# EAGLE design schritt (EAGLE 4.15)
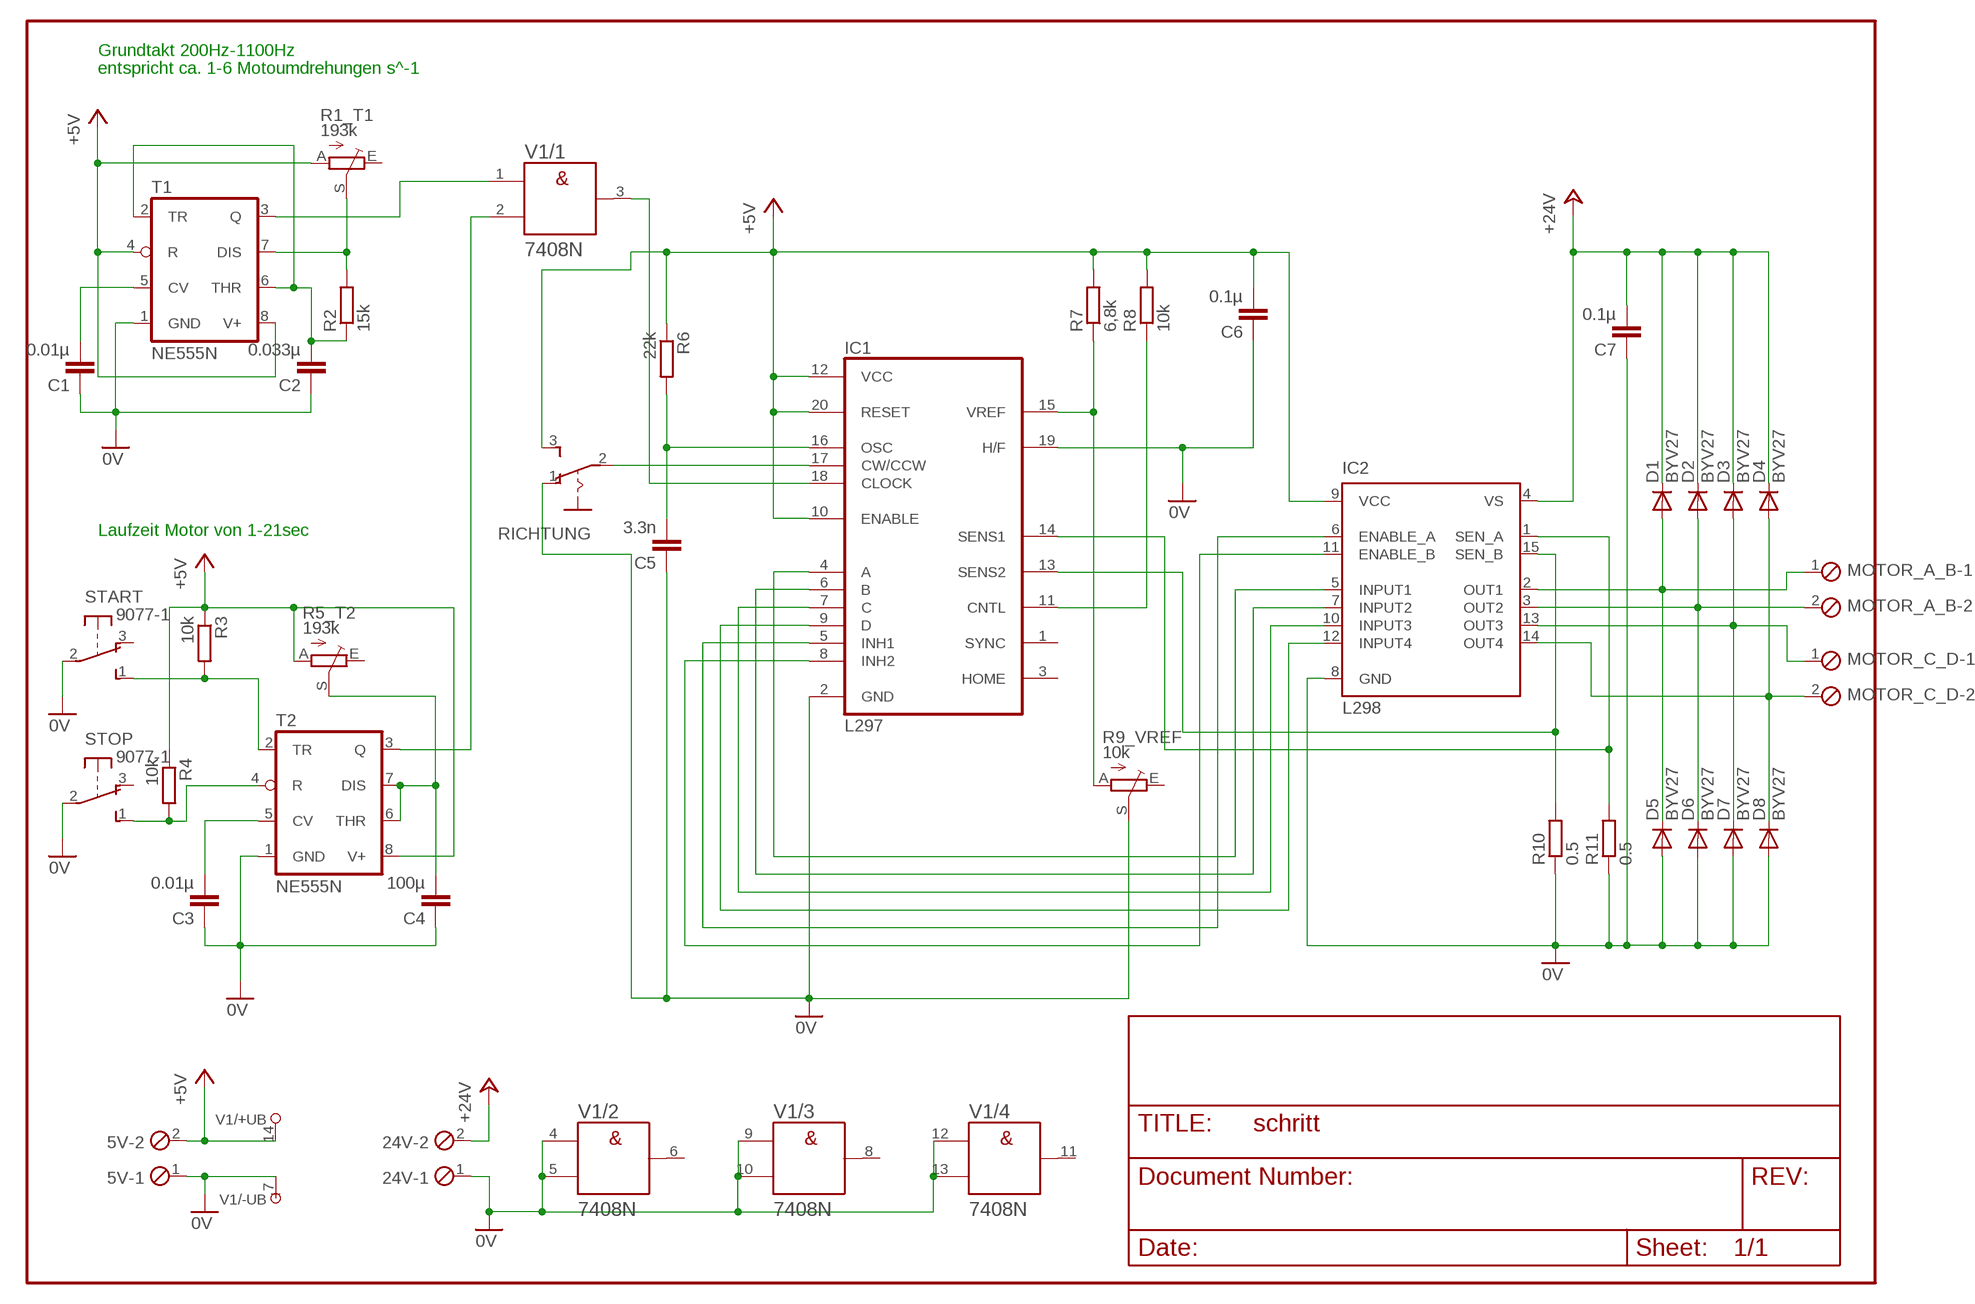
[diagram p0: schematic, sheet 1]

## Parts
5V  MPT2  [2POL254]
24V  MPT2  [2POL254]
C1  0.01µ  C-EU025-030X050  [C025-030X050]
C2  0.033µ  C-EU025-030X050  [C025-030X050]
C3  0.01µ  C-EU025-030X050  [C025-030X050]
C4  100µ  C-EU025-030X050  [C025-030X050]
C5  3.3n  C-EU025-030X050  [C025-030X050]
C6  0.1µ  C-EU025-030X050  [C025-030X050]
C7  0.1µ  C-EU025-030X050  [C025-030X050]
D1  BYV27  [SOD57-10]
D2  BYV27  [SOD57-10]
D3  BYV27  [SOD57-10]
D4  BYV27  [SOD57-10]
D5  BYV27  [SOD57-10]
D6  BYV27  [SOD57-10]
D7  BYV27  [SOD57-10]
D8  BYV27  [SOD57-10]
IC1  L297  [DIL20]
IC2  L298  [MULTIWATT-15]
MOTOR_A_B  MPT2  [2POL254]
MOTOR_C_D  MPT2  [2POL254]
R1_T1  193k  TRIM_EU-CA14H  [CA14H]
R2  15k  R-EU_0204/5  [0204/5]
R3  10k  R-EU_0204/5  [0204/5]
R4  10k  R-EU_0204/5  [0204/5]
R5_T2  193k  TRIM_EU-CA14H  [CA14H]
R6  22k  R-EU_0204/5  [0204/5]
R7  6,8k  R-EU_0204/5  [0204/5]
R8  10k  R-EU_0204/5  [0204/5]
R9_VREF  10k  TRIM_EU-B25U  [B25U]
R10  0.5  R-EU_0207/12  [0207/12]
R11  0.5  R-EU_0207/12  [0207/12]
RICHTUNG  255SB  [255SB]
START  9077-1  [9077-1]
STOP  9077-1  [9077-1]
T1  NE555N  [DIL08]
T2  NE555N  [DIL08]
V1  7408N  [DIL14]

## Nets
0V: 5V.1 24V.1 C1.1 C2.1 C3.1 C4.1 C5.1 C6.1 C7.1 D5.A D6.A D7.A D8.A IC1.2(GND) IC1.19(H/F) IC2.8(GND) R9_VREF.S R10.1 R11.1 RICHTUNG.1(O) START.2(P) STOP.2(P) T1.1(GND) T2.1(GND) V1.4(/2:A) V1.5(/2:B) V1.7(/-UB:-UB) V1.9(/3:A) V1.10(/3:B) V1.12(/4:A) V1.13(/4:B)
+5V: 5V.2 C6.2 IC1.10(ENABLE) IC1.12(VCC) IC1.20(RESET) IC2.9(VCC) R1_T1.A R3.1 R4.1 R5_T2.A R6.1 R7.2 R8.2 RICHTUNG.3(S) T1.4(R) T1.8(V+) T2.8(V+) V1.14(/+UB:+UB)
+24V: 24V.2 C7.2 D1.C D2.C D3.C D4.C IC2.4(VS)
N$1: T2.3(Q) V1.2(/1:B)
N$2: T1.3(Q) V1.1(/1:A)
N$3: C1.2 C3.2 T1.5(CV) T2.5(CV)
N$4: R1_T1.S R2.2 T1.7(DIS)
N$5: C2.2 R2.1 T1.2(TR) T1.6(THR)
N$7: IC1.18(CLOCK) V1.3(/1:Y)
N$8: R3.2 START.1(S) T2.2(TR)
N$9: R4.2 STOP.1(S) T2.4(R)
N$10: IC1.4(A) IC2.5(INPUT1)
N$11: IC1.6(B) IC2.7(INPUT2)
N$12: IC1.7(C) IC2.10(INPUT3)
N$13: IC1.9(D) IC2.12(INPUT4)
N$14: IC1.5(INH1) IC2.6(ENABLE_A)
N$15: C4.2 R5_T2.S T2.6(THR) T2.7(DIS)
N$16: IC1.8(INH2) IC2.11(ENABLE_B)
N$17: IC1.11(CNTL) R8.1
N$18: IC1.13(SENS2) IC2.15(SEN_B) R10.2
N$19: IC1.14(SENS1) IC2.1(SEN_A) R11.2
N$20: D1.A D5.C IC2.2(OUT1) MOTOR_A_B.1
N$21: IC1.17(CW/CCW) RICHTUNG.2(P)
N$22: IC1.15(VREF) R7.1 R9_VREF.A
N$23: C5.2 IC1.16(OSC) R6.2
N$24: D2.A D6.C IC2.3(OUT2) MOTOR_A_B.2
N$25: D3.A D7.C IC2.13(OUT3) MOTOR_C_D.1
N$26: D4.A D8.C IC2.14(OUT4) MOTOR_C_D.2
Unconnected: IC1.1(SYNC) IC1.3(HOME) R1_T1.E R5_T2.E R9_VREF.E START.3(O) STOP.3(O) V1.6(/2:Y) V1.8(/3:Y) V1.11(/4:Y)

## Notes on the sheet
- Grundtakt 200Hz-1100Hz
- entspricht ca. 1-6 Motoumdrehungen s^-1
- Laufzeit Motor von 1-21sec

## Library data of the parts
5V 24V MOTOR_A_B MOTOR_C_D = con-phoenix-254:MPT2: PHOENIX CONNECTOR
C1-C7 = rcl:C-EU: CAPACITOR, European symbol
D1-D8 = diode:BYV27: DIODE
IC1 = st-microelectronics:L297: STEPPER MOTOR CONTROLLER
IC2 = st-microelectronics:L298: DUAL FULL-BRIDGE DRIVER
R1_T1 R5_T2 R9_VREF = pot:TRIM_EU-: POTENTIOMETER
R2-R4 R6-R8 R10 R11 = rcl:R-EU_: RESISTOR, European symbol
RICHTUNG = switch:255SB: SLIDING SWITCH distributor Buerklin, 11G810
START STOP = switch-misc:9077-1: MARQUARDT SWITCH
T1 T2 = linear:*555: TIMER
V1 = 74ttl-din:74*08: Quad 2-input AND gate

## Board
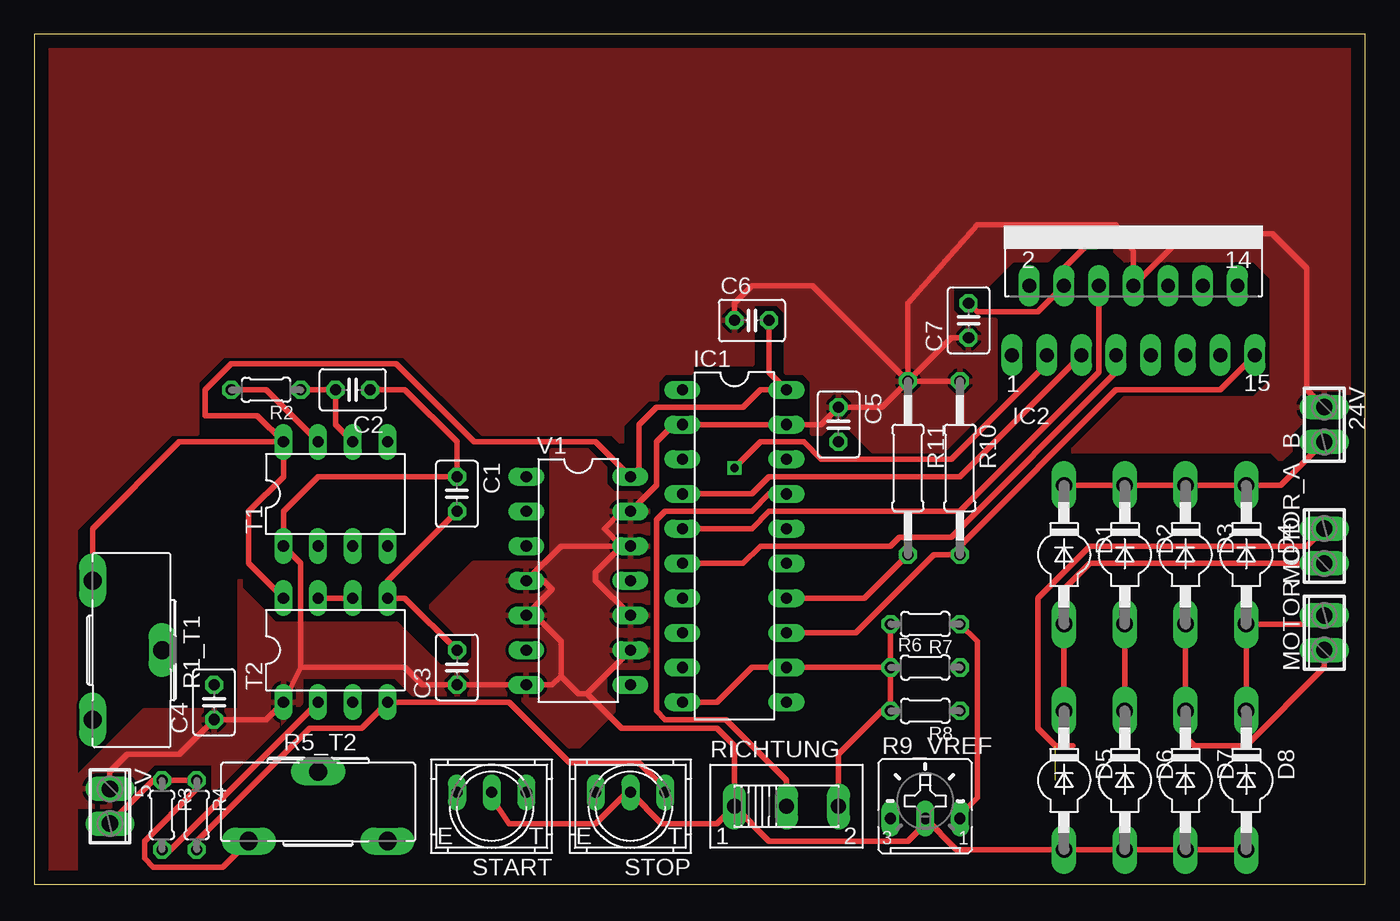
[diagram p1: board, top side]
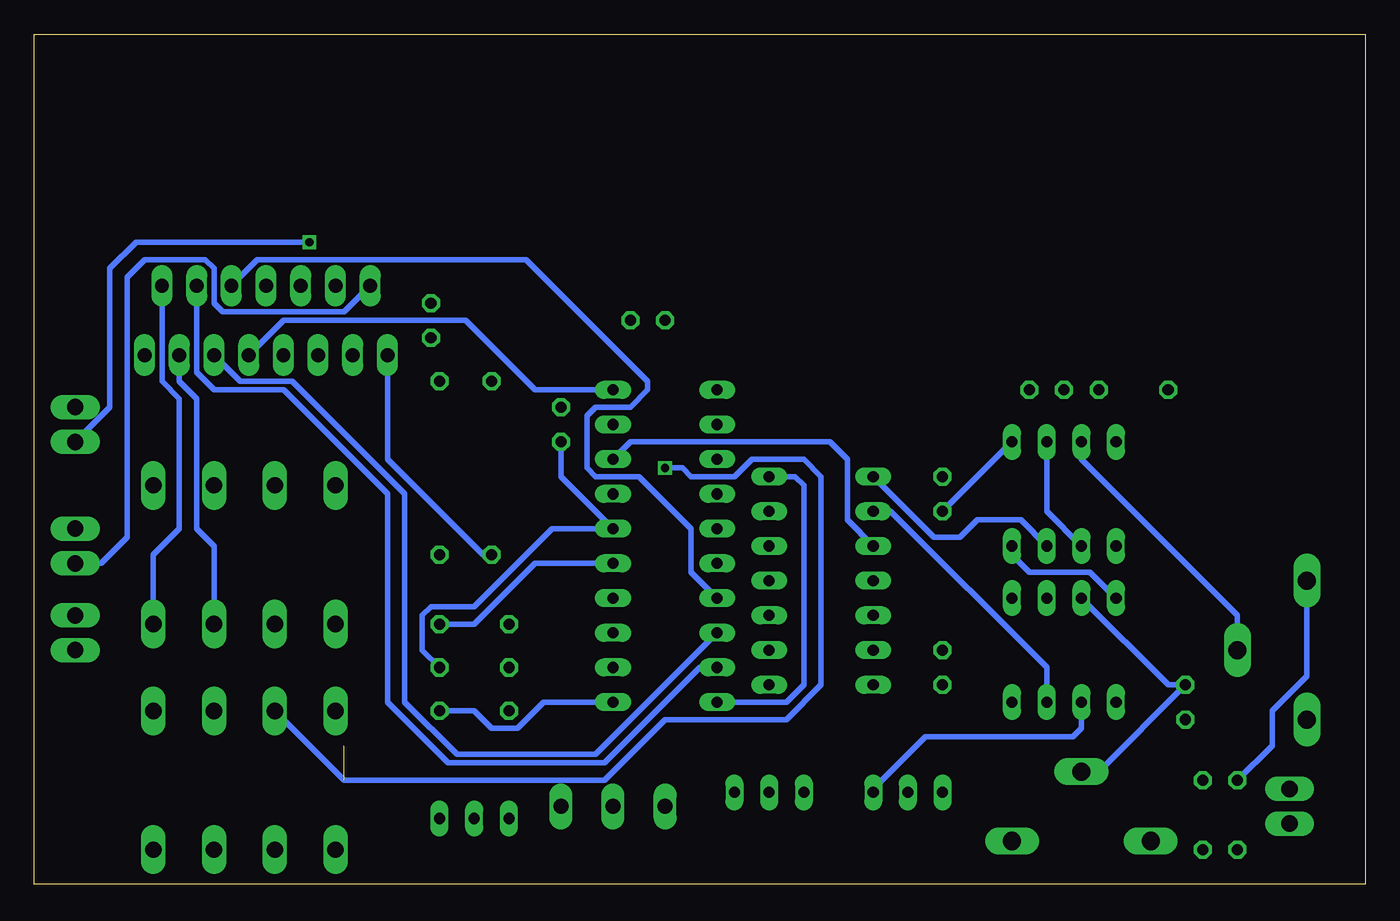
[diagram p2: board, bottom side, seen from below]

Size 97.46 x 62.22 mm. Coordinates in mm from the lower left corner, seen from the top.
Outline: 0,0 97.46,0 97.46,62.22 0,62.22 0,0
Copper layers (1*16): Top 0.035mm / dielectric 1.5mm / Bottom 0.035mm
Design rules "default": minimum track width 10mil, minimum drill 24mil, track to track 8mil, track to pad 8mil, pad to pad 8mil, via to via 8mil, smd to smd 8mil, copper to edge 40mil, drill to drill 8mil, minimum pad ring 10mil, minimum via ring 8mil, stop-mask expansion 4mil, vias tented up to drill 0mil, thermal gap 10mil

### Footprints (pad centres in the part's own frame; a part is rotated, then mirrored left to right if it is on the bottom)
2POL254 = drill 1.2 long: 1 -1.27,0; 2 1.27,0
C025-030X050 = drill 0.813 octagon: 1 -1.27,0; 2 1.27,0
SOD57-10 = drill 1.194 long: A 5.08,0; C -5.08,0
DIL20 = drill 0.813 long: 1 -11.43,-3.81; 2 -8.89,-3.81; 3 -6.35,-3.81; 4 -3.81,-3.81; 5 -1.27,-3.81; 6 1.27,-3.81; 7 3.81,-3.81; 8 6.35,-3.81; 9 8.89,-3.81; 10 11.43,-3.81; 11 11.43,3.81; 12 8.89,3.81; 13 6.35,3.81; 14 3.81,3.81; 15 1.27,3.81; 16 -1.27,3.81; 17 -3.81,3.81; 18 -6.35,3.81; 19 -8.89,3.81; 20 -11.43,3.81
MULTIWATT-15 = drill 1.016 long: 1 -8.89,-7.62; 2 -7.62,-2.54; 3 -6.35,-7.62; 4 -5.08,-2.54; 5 -3.81,-7.62; 6 -2.54,-2.54; 7 -1.27,-7.62; 8 0,-2.54; 9 1.27,-7.62; 10 2.54,-2.54; 11 3.81,-7.62; 12 5.08,-2.54; 13 6.35,-7.62; 14 7.62,-2.54; 15 8.89,-7.62
CA14H = drill 1.321 long: A -5.08,0; E 5.08,0; S 0,5.08
0204/5 = drill 0.813 octagon: 1 -2.54,0; 2 2.54,0
B25U = drill 0.813 long: A 2.54,-0.889; E -2.54,-0.889; S 0,-0.889
0207/12 = drill 0.813 octagon: 1 -6.35,0; 2 6.35,0
255SB = drill 1.118 long: 1 -3.81,0; 2 0,0; 3 3.81,0
9077-1 = drill 0.813 long: 1 -2.54,-1.016; 2 0,-1.016; 3 2.54,-1.016
DIL08 = drill 0.813 long: 1 -3.81,-3.81; 2 -1.27,-3.81; 3 1.27,-3.81; 4 3.81,-3.81; 5 3.81,3.81; 6 1.27,3.81; 7 -1.27,3.81; 8 -3.81,3.81
DIL14 = drill 0.813 long: 1 -7.62,-3.81; 2 -5.08,-3.81; 3 -2.54,-3.81; 4 0,-3.81; 5 2.54,-3.81; 6 5.08,-3.81; 7 7.62,-3.81; 8 7.62,3.81; 9 5.08,3.81; 10 2.54,3.81; 11 0,3.81; 12 -2.54,3.81; 13 -5.08,3.81; 14 -7.62,3.81

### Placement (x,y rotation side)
5V  5.55,5.71 270 top
24V  94.45,33.65 270 top
C1  30.95,28.57 270 top
C2  23.33,36.19 180 top
C3  30.95,15.87 90 top
C4  13.17,13.33 90 top
C5  58.89,33.65 270 top
C6  52.54,41.27 0 top
C7  68.41,41.27 90 top
D1  75.4,24.12 270 top
D2  79.84,24.12 270 top
D3  84.29,24.12 270 top
D4  88.73,24.12 270 top
D5  75.4,7.62 270 top
D6  79.84,7.62 270 top
D7  84.29,7.62 270 top
D8  88.73,7.62 270 top
IC1  51.27,24.76 270 top
IC2  80.48,46.35 0 top
MOTOR_A_B  94.45,24.76 90 top
MOTOR_C_D  94.45,18.41 90 top
R1_T1  4.28,17.14 270 top
R2  16.98,36.19 180 top
R3  9.36,5.08 270 top
R4  11.9,5.08 270 top
R5_T2  20.79,3.17 0 top
R6  65.24,15.87 0 top
R7  65.24,19.04 180 top
R8  65.24,12.7 180 top
R9_VREF  65.24,5.71 0 top
R10  67.78,30.47 270 top
R11  63.97,30.47 270 top
RICHTUNG  55.08,5.71 0 top
START  33.49,5.71 180 top
STOP  43.65,5.71 180 top
T1  22.06,28.57 0 top
T2  22.06,17.14 0 top
V1  39.84,22.22 270 top

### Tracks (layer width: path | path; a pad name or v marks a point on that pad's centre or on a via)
0V
  Top 0.406: 19.52,15.87 T2.1 16.98,12.06 C4.1 10.63,9.52 6.82,9.52 5.55,8.25 5V.1 | 19.52,15.87 19.52,23.49 T1.1 18.25,27.3 20.79,29.84 C1.1 30.95,32.38 27.14,36.19 C2.1 | 19.52,15.87 27.14,15.87 28.41,14.6 C3.1 V1.7 37.94,14.6 38.57,15.24 | START.2 33.49,6.34 34.76,4.44 41.11,4.44 43.65,6.98 STOP.2 45.94,4.44 50,4.44 RICHTUNG.1 | RICHTUNG.1 53.81,3.17 63.97,3.17 65.24,4.44 R9_VREF.S 67.53,2.54 D5.A D6.A D7.A D8.A | C6.1 51.27,42.54 52.54,43.81 56.98,43.81 R11.1 | 43.02,24.76 41.75,26.03 43.02,27.3 V1.13 45.55,29.2 45.55,32.38 46.83,33.65 IC1.2 IC1.19 57.62,33.65 C5.1 62.07,34.92 R11.1 | 38.57,15.24 38.57,17.77 36.66,19.68 V1.5 37.94,21.58 37.3,22.22 V1.4 38.57,24.76 V1.12 43.02,24.76 | V1.10 41.11,22.22 41.11,22.86 43.02,24.76 | R11.1 63.97,42.54 69.05,48.26 79.21,48.26 80.48,46.35 IC2.8 84.29,47.62 90.64,47.62 93.18,45.08 93.18,36.19 24V.1 | C7.1 67.14,40 R11.1 | R11.1 R10.1 | 40.48,13.97 V1.9 | 40.48,13.97 39.84,13.97 38.57,15.24 | RICHTUNG.1 51.27,10.16 50,11.43 43.02,11.43 40.48,13.97
  pour Top: 37.94,31.74 37.94,24.12 37.3,23.49 32.22,23.49 29.04,20.31 30.95,18.41 32.22,18.41 32.22,16.5 31.58,15.87 29.68,15.87 26.5,19.04 17.61,19.04 16.98,19.68 16.98,12.06 17.61,11.43 19.52,13.33 19.52,15.24 26.5,15.24 27.77,13.97 35.4,13.97 39.21,10.16 39.84,10.16 42.38,12.7 42.38,13.33 41.75,13.97 41.75,15.24 42.38,15.87 44.92,15.87 44.92,27.93 44.29,28.57 42.38,28.57 41.75,29.2 41.75,30.47 40.48,31.74
  pour Top: 17.61,11.43 13.17,6.98 13.17,8.89 8.72,8.89 5.55,5.71 3.01,5.71 3.01,7.62 8.09,12.7 17.61,12.7
  pour Top: 56.98,33.02 57.62,33.02 58.26,33.65 59.52,33.65 61.43,31.74 66.51,31.74 70.32,35.55 70.32,41.27 67.78,41.27 67.14,41.91 67.14,47.62 48.09,47.62 48.09,38.1 52.54,38.1 52.54,42.54 54.45,42.54 55.08,41.91 55.08,37.46 56.35,37.46 56.98,36.83 56.98,33.65
  pour Top: 48.09,38.1 48.09,37.46 46.19,37.46 45.55,36.83 45.55,35.55 44.92,35.55 43.02,33.65 43.02,32.38 42.38,33.02 32.85,33.02 27.14,38.73 13.8,38.73 11.9,36.83 11.9,33.02 10,33.02 3.01,26.03 3.01,0.63 0.47,0.63 0.47,61.59 96.99,61.59 96.99,34.29 93.18,34.29 91.91,33.02 91.91,31.74 91.27,31.11 90.64,31.74 76.03,31.74 79.84,35.55 89.37,35.55 90.64,36.83 90.64,44.45 89.37,45.72 79.84,45.72 79.21,46.35 79.21,46.98 78.57,47.62 77.94,48.26 76.67,48.26 74.13,45.72 71.59,45.72 70.95,45.08 69.68,43.81 67.14,43.81 50,43.81 49.37,43.81 48.73,43.18 48.73,39.37 48.09,38.73
+5V
  Top 0.406: T1.8 10.63,32.38 4.28,26.03 R1_T1.A | T1.8 18.25,29.84 15.71,27.3 15.71,23.49 T2.8 | T1.8 16.34,34.29 12.54,34.29 12.54,36.19 14.44,38.1 26.5,38.1 32.22,32.38 41.11,32.38 V1.14 44.29,30.47 44.29,33.65 45.55,34.92 51.91,34.92 53.18,36.19 IC1.20 53.81,37.46 C6.2 | IC1.10 50,13.33 52.54,15.87 IC1.12 R6.1 | RICHTUNG.3 58.89,9.52 62.07,12.7 R8.2 R6.1 | R6.1 R7.2 | 5V.2 8.72,7.62 R3.1 R4.1 11.9,6.98 8.09,3.17 8.09,1.9 8.72,1.27 13.8,1.27 R5_T2.A
  Bottom 0.406: T2.8 20.15,22.86 24.6,22.86 25.87,24.12 T1.4 | V1.14 41.75,29.84 41.11,29.2 41.11,14.6 42.38,13.33 IC1.10 | IC1.20 60.8,36.19 65.88,41.27 79.21,41.27 IC2.9 | R1_T1.A 4.28,15.24 6.82,12.7 6.82,10.16 R3.1
+24V  (via drill 0.6)
  Top 0.406: D1.C D2.C D3.C D4.C 91.27,29.2 24V.2 | C7.2 69.05,41.91 73.49,41.91 IC2.4 75.4,45.08 v77.3,46.98
  Bottom 0.406: v77.3,46.98 90,46.98 91.91,45.08 91.91,34.92 24V.2
N$1
  Bottom 0.406: V1.2 34.76,27.3 23.33,15.87 T2.3
N$2
  Bottom 0.406: T1.3 25.23,26.66 28.41,26.66 29.68,25.39 31.58,25.39 V1.1
N$3
  Top 0.406: C1.2 25.87,22.22 T2.5 27.14,20.95 C3.2
  Bottom 0.406: C1.2 T1.5
N$4
  Top 0.406: R2.2 16.98,36.19 T1.7
  Bottom 0.406: T1.7 20.79,31.11 9.36,19.68 R1_T1.S
N$5
  Top 0.406: R2.1 C2.2 22.06,33.65 T1.6
  Bottom 0.406: T1.6 23.33,27.3 T1.2
N$6  (via drill 0.6)
  other vias: 77.3,46.98
N$7
  Bottom 0.406: IC1.18 53.81,32.38 39.21,32.38 37.94,31.11 37.94,26.66 V1.3
N$8
  Top 0.406: R3.2 10,2.54 T2.2
  Bottom 0.406: T2.2 20.79,11.43 21.42,10.79 32.22,10.79 36.03,6.98 START.1
N$9
  Top 0.406: R4.2 11.9,3.17 20.15,11.43 23.96,11.43 T2.4 34.76,13.33 39.21,8.89 44.29,8.89 46.19,6.98 STOP.1
N$10
  Top 0.406: IC1.4 52.54,28.57 53.81,29.84 67.78,29.84 IC2.5
N$11
  Top 0.406: IC1.6 51.91,23.49 53.18,24.76 62.7,24.76 63.34,25.39 67.14,25.39 79.21,37.46 IC2.7
N$12
  Bottom 0.406: IC2.10 81.11,45.72 61.43,45.72 52.54,36.83 52.54,36.19 53.81,34.92 56.35,34.92 56.98,34.29 56.98,30.47 56.35,29.84 53.18,29.84 49.37,26.03 49.37,22.86 IC1.7
N$13
  Bottom 0.406: IC1.9 48.73,15.87 55.72,8.89 67.14,8.89 71.59,13.33 71.59,28.57 79.21,36.19 84.29,36.19 85.56,37.46 IC2.12
N$14
  Top 0.406: IC1.5 52.54,26.03 53.81,27.3 67.78,27.3 77.94,37.46 IC2.6
N$15
  Top 0.406: T2.7 T2.6
  Bottom 0.406: T2.7 14.44,14.6 C4.2 19.52,8.25 R5_T2.S
N$16
  Bottom 0.406: IC1.8 56.35,9.52 66.51,9.52 70.32,13.33 70.32,28.57 78.57,36.83 82.38,36.83 IC2.11
N$17
  Bottom 0.406: R8.1 65.24,12.7 63.97,11.43 62.07,11.43 60.16,13.33 IC1.11
N$18
  Top 0.406: IC1.13 60.16,18.41 65.88,24.12 R10.2 67.78,24.76 79.21,36.19 86.83,36.19 IC2.15
N$19
  Top 0.406: IC1.14 60.8,20.95 R11.2
  Bottom 0.406: R11.2 64.61,24.12 71.59,31.11 IC2.1
N$20
  Top 0.406: D5.C D1.A 75.4,21.58 77.3,23.49 MOTOR_A_B.1
  Bottom 0.406: IC2.2 74.77,41.91 83.66,41.91 84.29,42.54 84.29,45.08 84.92,45.72 89.37,45.72 90.64,44.45 90.64,25.39 92.55,23.49 MOTOR_A_B.1
N$21
  Top 0.406: IC1.17 53.81,28.57 52.54,27.3 46.19,27.3 45.55,26.66 45.55,12.7 46.19,12.06 50.64,12.06 55.08,7.62 RICHTUNG.2
N$22
  Top 0.406: R7.1 69.05,17.77 69.05,6.34 67.78,5.08 R9_VREF.A
  Bottom 0.406: IC1.15 60.8,23.49 65.24,19.04 R7.1
N$23
  Bottom 0.406: C5.2 58.89,29.84 IC1.16 59.52,26.03 65.24,20.31 68.41,20.31 69.05,19.68 69.05,17.14 R6.2
N$24  (via drill 0.6)  (1 unrouted)
  Top 0.406: D6.C D2.A 79.84,13.97 | 76.03,10.16 74.77,10.16 73.49,11.43 73.49,20.95 77.3,24.76 93.18,24.76 MOTOR_A_B.2 | IC2.3 74.13,38.1 67.14,31.11 57.62,31.11 56.35,32.38 53.18,32.38 v51.27,30.47
  Bottom 0.406: v51.27,30.47 50,30.47 49.37,29.84 46.19,29.84 44.92,31.11 41.11,31.11 39.84,29.84 39.84,14.6 42.38,12.06 51.27,12.06 55.72,7.62 74.77,7.62 D6.C
N$25
  Top 0.406: D7.C D3.A 84.29,10.79 84.92,10.16 88.73,10.16 94.45,15.87 MOTOR_C_D.1
  Bottom 0.406: IC2.13 86.83,36.83 85.56,35.55 85.56,26.03 84.29,24.76 D3.A
N$26
  Top 0.406: D8.C D4.A 93.81,19.04 MOTOR_C_D.2
  Bottom 0.406: IC2.14 88.1,36.83 86.83,35.55 86.83,26.03 88.73,24.12 88.73,20.95 | 88.73,20.95 88.73,19.68 | D4.A 88.73,20.95
N$27
  pour Top: 15.08,12.7 15.08,22.22 15.08,21.58 16.98,19.68 16.98,12.06 15.71,12.06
